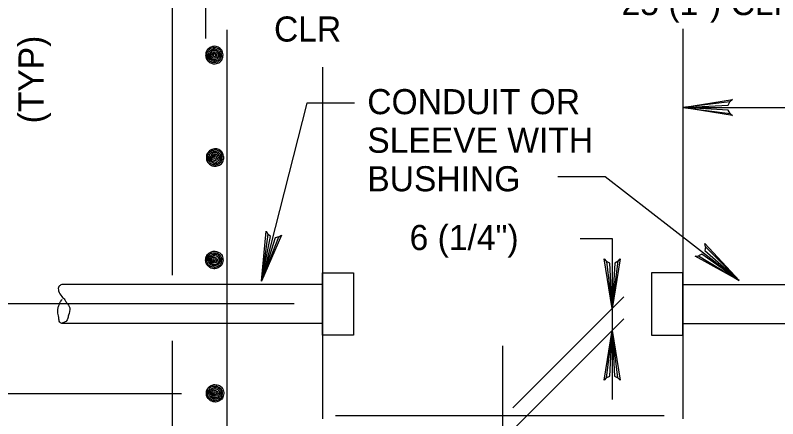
# Model space of a CAD drawing. Extents: x 638455 to 640199, y 298558 to 299152.
# Drawn here: x 639434 to 639536, y 298695 to 298749 of the extents above; entities that cross this region are included whole.
import ezdxf

# ---------------------------------------------------------------- set-up
doc = ezdxf.new("R2010")
doc.units = 0
doc.layers.add('2', color=7, linetype='Continuous')
doc.layers.add('3', color=7, linetype='Continuous')

msp = doc.modelspace()

# ---------------------------------------------------------------- linework, layer by layer
at = {"layer": '2'}
for p, q in [((639454.98, 298775.09), (639454.98, 298714.23)), ((639459.45, 298752.82), (639459.45, 298745.89)), ((639462.3, 298747.08), (639462.3, 298688.79)), ((639523.29, 298747.2), (639523.29, 298695.02)), ((639475.08, 298742.06), (639475.08, 298695.02)), ((639523.29, 298736.67), (639543.38, 298736.67)), ((639509.55, 298719.14), (639513.85, 298719.14)), ((639513.85, 298719.14), (639513.85, 298709.77)), ((639475.08, 298712.99), (639440.23, 298712.99)), ((639475.08, 298712.99), (639443.95, 298712.99)), ((639523.29, 298712.99), (639556.64, 298712.99)), ((639500.54, 298696.46), (639515.41, 298711.34)), ((639435.18, 298710.38), (639429.68, 298710.38)), ((639471.3, 298710.38), (639435.18, 298710.38)), ((639513.85, 298709.77), (639513.85, 298706.82)), ((639475.08, 298707.77), (639440.23, 298707.77)), ((639475.08, 298707.77), (639443.95, 298707.77)), ((639500.37, 298693.34), (639515.41, 298708.39)), ((639523.29, 298707.77), (639557.04, 298707.77)), ((639513.85, 298706.82), (639513.85, 298697.6)), ((639523.29, 298706.9), (639523.29, 298706.9)), ((639475.08, 298706.2), (639475.08, 298706.2)), ((639523.29, 298706.2), (639523.29, 298706.2)), ((639454.98, 298705.43), (639454.98, 298676.53)), ((639499.18, 298704.79), (639499.18, 298643.37)), ((639456.25, 298698.37), (639413.51, 298698.37)), ((639476.84, 298695.47), (639520.78, 298695.47))]:
    msp.add_line(p, q, dxfattribs=at)
for points in [[(639479.37, 298737.24), (639473, 298737.24), (639466.92, 298713.43)], [(639529.62, 298735.88), (639529.38, 298736.34), (639523.29, 298736.67), (639529.62, 298735.88), (639529.94, 298735.6), (639523.29, 298736.67), (639529.38, 298736.97), (639529.6, 298737.43), (639523.29, 298736.67), (639529.94, 298737.73), (639529.6, 298737.43)], [(639506.56, 298727.44), (639512.92, 298727.44), (639530.82, 298713.51)], [(639469.27, 298719.36), (639468.77, 298719.24), (639466.92, 298713.43), (639469.27, 298719.36), (639469.62, 298719.6), (639466.92, 298713.43), (639468.15, 298719.4), (639467.77, 298719.73), (639466.92, 298713.43), (639467.56, 298720.13), (639467.77, 298719.73)], [(639526.33, 298718.04), (639526.23, 298717.54), (639530.82, 298713.51), (639526.33, 298718.04), (639526.24, 298718.46), (639530.82, 298713.51), (639525.84, 298717.03), (639525.39, 298716.81), (639530.82, 298713.51), (639524.93, 298716.78), (639525.39, 298716.81)], [(639514.64, 298716.1), (639514.19, 298715.86), (639513.85, 298709.77), (639514.64, 298716.1), (639514.92, 298716.43), (639513.85, 298709.77), (639513.55, 298715.86), (639513.09, 298716.08), (639513.85, 298709.77), (639512.79, 298716.43), (639513.09, 298716.08)], [(639513.05, 298700.49), (639513.51, 298700.73), (639513.85, 298706.82), (639513.05, 298700.49), (639512.78, 298700.17), (639513.85, 298706.82), (639514.15, 298700.73), (639514.6, 298700.51), (639513.85, 298706.82), (639514.91, 298700.17), (639514.6, 298700.51)]]:
    msp.add_lwpolyline(points, dxfattribs=at)
for points in [[(639475.08, 298706.2), (639475.08, 298714.56), (639479.26, 298714.56), (639479.26, 298706.2)], [(639523.29, 298706.2), (639523.29, 298714.56), (639519.1, 298714.56), (639519.1, 298706.2)]]:
    msp.add_lwpolyline(points, close=True, dxfattribs=at)
for points in [[(639460.62, 298743.69), (639460.57, 298743.81), (639460.48, 298743.79), (639460.46, 298743.61), (639460.62, 298743.51), (639460.82, 298743.61), (639460.81, 298743.79), (639460.7, 298743.91), (639460.48, 298743.92), (639460.33, 298743.81), (639460.25, 298743.62), (639460.36, 298743.37), (639460.6, 298743.32), (639460.87, 298743.4), (639461.01, 298743.57), (639460.99, 298743.85), (639460.86, 298744.03), (639460.62, 298744.1), (639460.41, 298744.06), (639460.23, 298743.95), (639460.15, 298743.76), (639460.11, 298743.52), (639460.16, 298743.3), (639460.37, 298743.16), (639460.69, 298743.09), (639461.04, 298743.24), (639461.21, 298743.48), (639461.21, 298743.81), (639461.1, 298744.09), (639460.86, 298744.28), (639460.48, 298744.3), (639460.21, 298744.15), (639460.04, 298743.88), (639459.94, 298743.61), (639459.99, 298743.28), (639460.21, 298743.05), (639460.52, 298742.92), (639461.03, 298743), (639461.34, 298743.27), (639461.41, 298743.66), (639461.34, 298744.03), (639461.12, 298744.33), (639460.83, 298744.45), (639460.37, 298744.44), (639460.01, 298744.23), (639459.84, 298743.92), (639459.79, 298743.6), (639459.82, 298743.32), (639459.93, 298743.01), (639460.23, 298742.8), (639460.71, 298742.73), (639461.14, 298742.85), (639461.46, 298743.15), (639461.58, 298743.49), (639461.55, 298743.94), (639461.41, 298744.35), (639461.17, 298744.53), (639460.74, 298744.68), (639460.3, 298744.62), (639459.99, 298744.47), (639459.76, 298744.2), (639459.63, 298743.92), (639459.63, 298743.61), (639459.65, 298743.28), (639459.72, 298742.97), (639459.88, 298742.8), (639460.12, 298742.65), (639460.36, 298742.56), (639460.6, 298742.52), (639460.91, 298742.57), (639461.21, 298742.67), (639461.48, 298742.86), (639461.66, 298743.11), (639461.75, 298743.43), (639461.79, 298743.72), (639461.73, 298744.06), (639461.61, 298744.33), (639461.39, 298744.58), (639461.12, 298744.75), (639460.86, 298744.85), (639460.55, 298744.86), (639460.18, 298744.77), (639459.88, 298744.58), (639459.69, 298744.38), (639459.54, 298744.13), (639459.48, 298743.87), (639459.47, 298743.57), (639459.54, 298743.24), (639459.63, 298743.09), (639459.84, 298742.86)], [(639460.72, 298729.98), (639460.67, 298730.1), (639460.58, 298730.08), (639460.56, 298729.9), (639460.72, 298729.8), (639460.92, 298729.9), (639460.91, 298730.08), (639460.8, 298730.19), (639460.58, 298730.21), (639460.42, 298730.1), (639460.35, 298729.91), (639460.46, 298729.66), (639460.7, 298729.6), (639460.97, 298729.69), (639461.11, 298729.85), (639461.1, 298730.14), (639460.96, 298730.33), (639460.72, 298730.39), (639460.51, 298730.35), (639460.33, 298730.24), (639460.25, 298730.05), (639460.21, 298729.81), (639460.26, 298729.59), (639460.47, 298729.45), (639460.79, 298729.38), (639461.14, 298729.53), (639461.31, 298729.77), (639461.31, 298730.1), (639461.2, 298730.38), (639460.96, 298730.57), (639460.58, 298730.59), (639460.31, 298730.44), (639460.14, 298730.17), (639460.04, 298729.9), (639460.09, 298729.57), (639460.31, 298729.34), (639460.62, 298729.2), (639461.13, 298729.29), (639461.44, 298729.56), (639461.51, 298729.94), (639461.44, 298730.33), (639461.22, 298730.62), (639460.93, 298730.74), (639460.47, 298730.73), (639460.11, 298730.52), (639459.93, 298730.21), (639459.89, 298729.89), (639459.92, 298729.6), (639460.03, 298729.3), (639460.33, 298729.09), (639460.81, 298729.02), (639461.24, 298729.14), (639461.55, 298729.44), (639461.68, 298729.78), (639461.65, 298730.23), (639461.51, 298730.64), (639461.27, 298730.82), (639460.85, 298730.97), (639460.4, 298730.9), (639460.1, 298730.76), (639459.86, 298730.49), (639459.73, 298730.2), (639459.73, 298729.9), (639459.75, 298729.57), (639459.82, 298729.26), (639459.98, 298729.09), (639460.22, 298728.94), (639460.46, 298728.85), (639460.7, 298728.81), (639461.01, 298728.86), (639461.31, 298728.95), (639461.58, 298729.15), (639461.76, 298729.4), (639461.85, 298729.71), (639461.89, 298730.01), (639461.83, 298730.35), (639461.71, 298730.62), (639461.49, 298730.87), (639461.22, 298731.04), (639460.96, 298731.14), (639460.65, 298731.14), (639460.28, 298731.06), (639459.98, 298730.87), (639459.79, 298730.67), (639459.64, 298730.42), (639459.58, 298730.16), (639459.57, 298729.85), (639459.64, 298729.53), (639459.73, 298729.37), (639459.93, 298729.15)], [(639460.62, 298716.27), (639460.57, 298716.15), (639460.48, 298716.16), (639460.46, 298716.35), (639460.62, 298716.45), (639460.82, 298716.35), (639460.81, 298716.16), (639460.7, 298716.05), (639460.48, 298716.03), (639460.33, 298716.15), (639460.25, 298716.34), (639460.36, 298716.59), (639460.6, 298716.64), (639460.87, 298716.56), (639461.01, 298716.39), (639460.99, 298716.11), (639460.86, 298715.92), (639460.62, 298715.86), (639460.41, 298715.9), (639460.23, 298716.01), (639460.15, 298716.2), (639460.11, 298716.44), (639460.16, 298716.66), (639460.37, 298716.8), (639460.69, 298716.86), (639461.04, 298716.72), (639461.21, 298716.48), (639461.21, 298716.15), (639461.1, 298715.87), (639460.86, 298715.68), (639460.48, 298715.66), (639460.21, 298715.81), (639460.04, 298716.07), (639459.94, 298716.35), (639459.99, 298716.68), (639460.21, 298716.91), (639460.52, 298717.04), (639461.03, 298716.96), (639461.34, 298716.69), (639461.41, 298716.3), (639461.34, 298715.92), (639461.12, 298715.63), (639460.83, 298715.51), (639460.37, 298715.52), (639460.01, 298715.73), (639459.84, 298716.03), (639459.79, 298716.36), (639459.82, 298716.64), (639459.93, 298716.95), (639460.23, 298717.16), (639460.71, 298717.23), (639461.14, 298717.11), (639461.46, 298716.81), (639461.58, 298716.46), (639461.55, 298716.02), (639461.41, 298715.61), (639461.17, 298715.43), (639460.74, 298715.28), (639460.3, 298715.34), (639459.99, 298715.49), (639459.76, 298715.76), (639459.63, 298716.04), (639459.63, 298716.35), (639459.65, 298716.68), (639459.72, 298716.99), (639459.88, 298717.16), (639460.12, 298717.31), (639460.36, 298717.4), (639460.6, 298717.44), (639460.91, 298717.39), (639461.21, 298717.29), (639461.48, 298717.1), (639461.66, 298716.85), (639461.75, 298716.53), (639461.79, 298716.24), (639461.73, 298715.9), (639461.61, 298715.63), (639461.39, 298715.38), (639461.12, 298715.21), (639460.86, 298715.11), (639460.55, 298715.1), (639460.18, 298715.19), (639459.88, 298715.38), (639459.69, 298715.57), (639459.54, 298715.82), (639459.48, 298716.09), (639459.47, 298716.39), (639459.54, 298716.72), (639459.63, 298716.87), (639459.84, 298717.1)], [(639440.23, 298712.99), (639439.83, 298712.7), (639439.79, 298712.14), (639440.24, 298711.37), (639440.61, 298710.94), (639440.86, 298710.55), (639441.29, 298709.86), (639441.12, 298708.87), (639440.99, 298708.36), (639440.69, 298707.97), (639440.27, 298707.8), (639440.23, 298707.77)], [(639440.23, 298707.77), (639440.03, 298707.84), (639439.84, 298708.35), (639439.78, 298708.77), (639439.7, 298709.17), (639439.7, 298709.6), (639439.78, 298710.04), (639439.9, 298710.34), (639440.03, 298710.69), (639440.08, 298710.76), (639440.16, 298710.87), (639440.29, 298710.99)], [(639460.72, 298698.43), (639460.67, 298698.31), (639460.58, 298698.32), (639460.56, 298698.5), (639460.72, 298698.6), (639460.92, 298698.5), (639460.91, 298698.32), (639460.8, 298698.21), (639460.58, 298698.19), (639460.42, 298698.31), (639460.35, 298698.5), (639460.46, 298698.75), (639460.7, 298698.8), (639460.97, 298698.72), (639461.11, 298698.55), (639461.1, 298698.26), (639460.96, 298698.08), (639460.72, 298698.01), (639460.51, 298698.06), (639460.33, 298698.17), (639460.25, 298698.35), (639460.21, 298698.59), (639460.26, 298698.82), (639460.47, 298698.96), (639460.79, 298699.02), (639461.14, 298698.88), (639461.31, 298698.64), (639461.31, 298698.31), (639461.2, 298698.03), (639460.96, 298697.84), (639460.58, 298697.82), (639460.31, 298697.97), (639460.14, 298698.23), (639460.04, 298698.5), (639460.09, 298698.84), (639460.31, 298699.07), (639460.62, 298699.2), (639461.13, 298699.12), (639461.44, 298698.84), (639461.51, 298698.46), (639461.44, 298698.08), (639461.22, 298697.79), (639460.93, 298697.67), (639460.47, 298697.68), (639460.11, 298697.89), (639459.93, 298698.19), (639459.89, 298698.52), (639459.92, 298698.8), (639460.03, 298699.1), (639460.33, 298699.32), (639460.81, 298699.38), (639461.24, 298699.26), (639461.55, 298698.97), (639461.68, 298698.62), (639461.65, 298698.18), (639461.51, 298697.76), (639461.27, 298697.59), (639460.85, 298697.44), (639460.4, 298697.5), (639460.1, 298697.65), (639459.86, 298697.92), (639459.73, 298698.2), (639459.73, 298698.5), (639459.75, 298698.84), (639459.82, 298699.14), (639459.98, 298699.32), (639460.22, 298699.47), (639460.46, 298699.56), (639460.7, 298699.59), (639461.01, 298699.55), (639461.31, 298699.45), (639461.58, 298699.25), (639461.76, 298699), (639461.85, 298698.69), (639461.89, 298698.4), (639461.83, 298698.06), (639461.71, 298697.79), (639461.49, 298697.54), (639461.22, 298697.37), (639460.96, 298697.27), (639460.65, 298697.26), (639460.28, 298697.35), (639459.98, 298697.54), (639459.79, 298697.73), (639459.64, 298697.98), (639459.58, 298698.25), (639459.57, 298698.55), (639459.64, 298698.88), (639459.73, 298699.03), (639459.93, 298699.25)]]:
    msp.add_spline(points, degree=3, dxfattribs=at)

# ---------------------------------------------------------------- texts
at = {"layer": '3'}
for s, p in [('25 (1") CLR', (639515.11, 298749.04)), ('CLR', (639468.61, 298745.5)), ('CONDUIT OR', (639481.09, 298735.78)), ('SLEEVE WITH', (639481.09, 298730.62)), ('BUSHING', (639481.09, 298725.46)), ('6 (1/4")', (639486.75, 298717.6))]:
    msp.add_text(s, height=3.36, dxfattribs=at).set_placement(p)
msp.add_text('(TYP)', height=3.36, rotation=90, dxfattribs=at).set_placement((639437.79, 298734.55))

doc.saveas('drawing.dxf')
